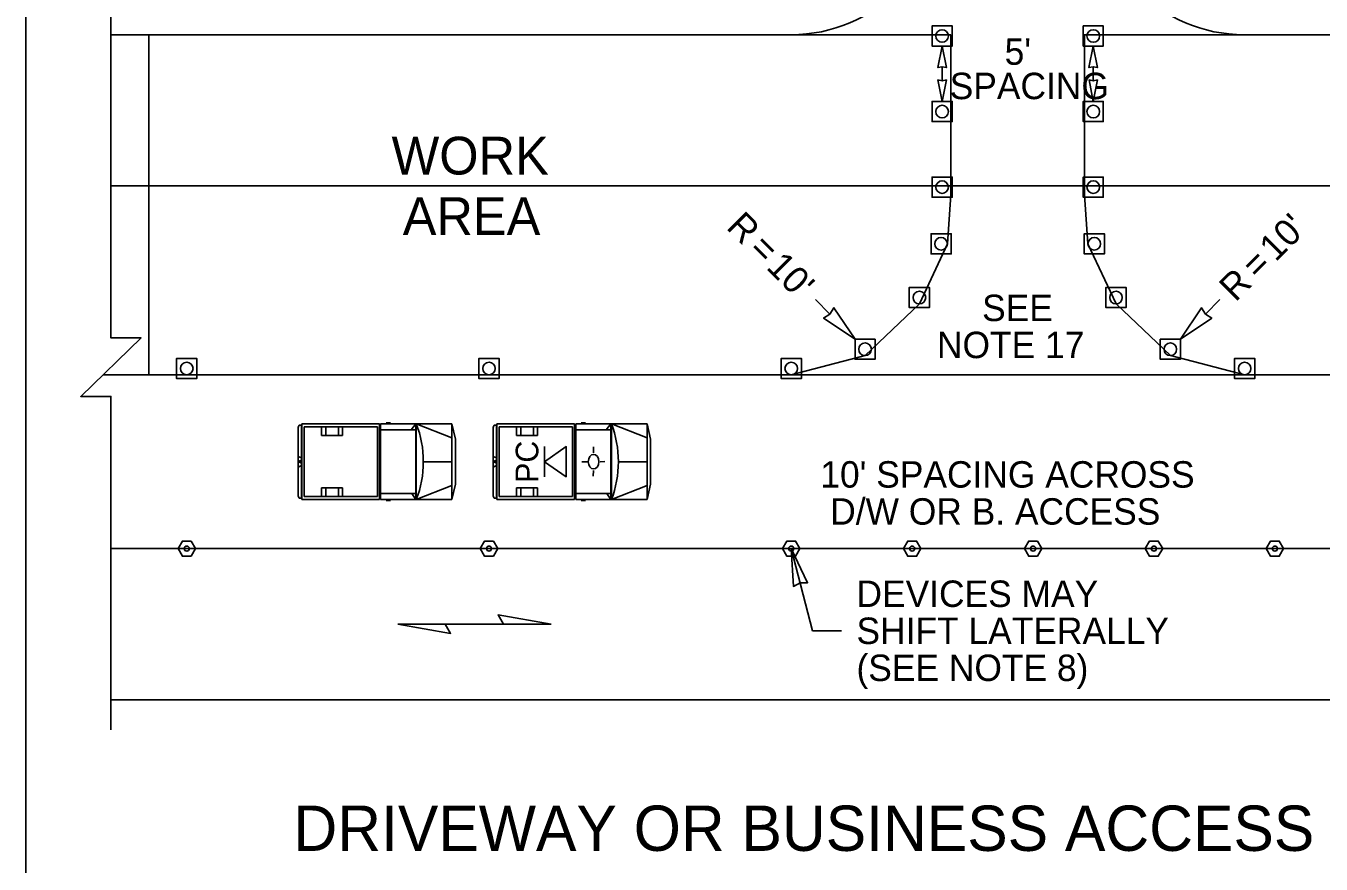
# Model space of a CAD drawing. Extents: x 99999.1 to 100095.7, y 99995 to 100010.7.
# Drawn here: x 100070.5 to 100073.928, y 100006.235 to 100008.454 of the extents above; entities that cross this region are included whole.
import ezdxf

# ---------------------------------------------------------------- set-up
doc = ezdxf.new("R2010")
doc.units = 0
for name, color, linetype in [('RD_ED_DrivewayEdge', 7, 'Continuous'), ('RD_ED_ShoulderPavedEdge', 7, 'Continuous'), ('RD_MK_LineEdgeWhite', 7, 'Continuous'), ('RD_MK_LineSkipCenter', 7, 'Continuous'), ('SH_DE_DetailHeading2Text', 7, 'Continuous'), ('TR_WZ_MotoristVehicle', 7, 'Continuous'), ('TR_WZ_PortableSignMountBlk-Wht', 7, 'Continuous'), ('TR_WZ_TrafficCone', 7, 'Continuous'), ('TR_WZ_TubularMarker', 7, 'Continuous'), ('TR_WZ_WorkAreaLabel', 7, 'Continuous'), ('TR_WZ_WorkZoneDetails', 7, 'Continuous'), ('TR_WZ_WorkZoneTextCurrent', 7, 'Continuous')]:
    doc.layers.add(name, color=color, linetype=linetype)

msp = doc.modelspace()

# ---------------------------------------------------------------- linework, layer by layer
at = {"layer": 'RD_ED_DrivewayEdge'}
for centre, start, end in [((100072.525, 100008.8304), 270, 0), ((100073.725, 100008.8304), 180, 270)]:
    msp.add_arc(centre, 0.4, start, end, dxfattribs=at)
at = {"layer": 'RD_ED_ShoulderPavedEdge'}
for p, q in [((100070.725, 100008.4305), (100072.525, 100008.4305)), ((100073.725, 100008.4305), (100075.525, 100008.4305)), ((100070.725, 100006.6704), (100075.525, 100006.6704))]:
    msp.add_line(p, q, dxfattribs=at)
at = {"layer": 'RD_MK_LineEdgeWhite'}
for p, q in [((100070.725, 100008.0305), (100075.525, 100008.0305)), ((100070.725, 100007.0704), (100075.525, 100007.0704))]:
    msp.add_line(p, q, dxfattribs=at)
at = {"layer": 'RD_MK_LineSkipCenter'}
msp.add_lwpolyline([(100075.5043, 100007.5305), (100070.7043, 100007.5305)], dxfattribs=at)
at = {"layer": 'TR_WZ_MotoristVehicle'}
for p, q in [((100071.2207, 100007.3911), (100071.2207, 100007.2098)), ((100071.2252, 100007.3972), (100071.2297, 100007.3972)), ((100071.2297, 100007.3972), (100071.2297, 100007.2037)), ((100071.2304, 100007.4005), (100071.4361, 100007.4005)), ((100071.2304, 100007.4005), (100071.2304, 100007.2005)), ((100071.2362, 100007.3925), (100071.2362, 100007.2084)), ((100071.2362, 100007.3925), (100071.4302, 100007.3925)), ((100071.2826, 100007.3925), (100071.2826, 100007.3695)), ((100071.2936, 100007.3925), (100071.2936, 100007.3695)), ((100071.3276, 100007.3925), (100071.3276, 100007.3695)), ((100071.3375, 100007.3925), (100071.3375, 100007.3695)), ((100071.4302, 100007.3925), (100071.4302, 100007.2084)), ((100071.4361, 100007.4005), (100071.4361, 100007.2005)), ((100071.4388, 100007.4005), (100071.4388, 100007.2005)), ((100071.6277, 100007.4005), (100071.4388, 100007.4005)), ((100071.5316, 100007.385), (100071.4388, 100007.385)), ((100071.4646, 100007.4033), (100071.4533, 100007.4033)), ((100071.5316, 100007.4005), (100071.5195, 100007.385)), ((100071.5316, 100007.4005), (100071.5316, 100007.2005)), ((100071.5333, 100007.4005), (100071.5333, 100007.2005)), ((100071.6277, 100007.3638), (100071.5333, 100007.4005)), ((100071.6277, 100007.4005), (100071.6277, 100007.2005)), ((100071.6277, 100007.4005), (100071.637, 100007.3601)), ((100071.737, 100007.3911), (100071.737, 100007.2098)), ((100071.7415, 100007.3972), (100071.7459, 100007.3972)), ((100071.7459, 100007.3972), (100071.7459, 100007.2037)), ((100071.7466, 100007.4005), (100071.9523, 100007.4005)), ((100071.7466, 100007.4005), (100071.7466, 100007.2005)), ((100071.7525, 100007.3925), (100071.7525, 100007.2084)), ((100071.7525, 100007.3925), (100071.9465, 100007.3925)), ((100071.7988, 100007.3925), (100071.7988, 100007.3695)), ((100071.8098, 100007.3925), (100071.8098, 100007.3695)), ((100071.8438, 100007.3925), (100071.8438, 100007.3695)), ((100071.8538, 100007.3925), (100071.8538, 100007.3695)), ((100071.9465, 100007.3925), (100071.9465, 100007.2084)), ((100071.9523, 100007.4005), (100071.9523, 100007.2005)), ((100071.9551, 100007.4005), (100071.9551, 100007.2005)), ((100072.144, 100007.4005), (100071.9551, 100007.4005)), ((100072.0478, 100007.385), (100071.9551, 100007.385)), ((100071.9809, 100007.4033), (100071.9695, 100007.4033)), ((100072.0478, 100007.4005), (100072.0358, 100007.385)), ((100072.0478, 100007.4005), (100072.0478, 100007.2005)), ((100072.0495, 100007.4005), (100072.0495, 100007.2005)), ((100072.144, 100007.3638), (100072.0495, 100007.4005)), ((100072.144, 100007.4005), (100072.144, 100007.2005)), ((100072.144, 100007.4005), (100072.1533, 100007.3601)), ((100071.2826, 100007.3695), (100071.3375, 100007.3695)), ((100071.637, 100007.3601), (100071.637, 100007.2408)), ((100071.7988, 100007.3695), (100071.8538, 100007.3695)), ((100072.0025, 100007.3401), (100072.0025, 100007.3239)), ((100072.1533, 100007.3601), (100072.1533, 100007.2408)), ((100071.2207, 100007.3145), (100071.2297, 100007.3108)), ((100071.2252, 100007.3033), (100071.2252, 100007.2976)), ((100071.737, 100007.3145), (100071.7459, 100007.3108)), ((100071.7415, 100007.3033), (100071.7415, 100007.2976)), ((100071.2207, 100007.2864), (100071.2297, 100007.2901)), ((100071.2231, 100007.3005), (100071.2273, 100007.3005)), ((100071.6277, 100007.3005), (100071.5518, 100007.3005)), ((100071.737, 100007.2864), (100071.7459, 100007.2901)), ((100071.7394, 100007.3005), (100071.7435, 100007.3005)), ((100071.9716, 100007.2997), (100071.9865, 100007.3001)), ((100071.9884, 100007.3001), (100071.9884, 100007.3001)), ((100072.0018, 100007.262), (100072.0021, 100007.277)), ((100072.0326, 100007.3006), (100072.02, 100007.3005)), ((100072.144, 100007.3005), (100072.0681, 100007.3005)), ((100071.6277, 100007.2371), (100071.5333, 100007.2005)), ((100071.6277, 100007.2005), (100071.637, 100007.2408)), ((100072.144, 100007.2371), (100072.0495, 100007.2005)), ((100072.144, 100007.2005), (100072.1533, 100007.2408)), ((100071.2252, 100007.2037), (100071.2297, 100007.2037)), ((100071.2304, 100007.2005), (100071.4361, 100007.2005)), ((100071.2362, 100007.2084), (100071.4302, 100007.2084)), ((100071.2826, 100007.2084), (100071.2826, 100007.2314)), ((100071.2826, 100007.2314), (100071.3375, 100007.2314)), ((100071.2936, 100007.2084), (100071.2936, 100007.2314)), ((100071.3276, 100007.2084), (100071.3276, 100007.2314)), ((100071.3375, 100007.2084), (100071.3375, 100007.2314)), ((100071.5316, 100007.216), (100071.4388, 100007.216)), ((100071.6277, 100007.2005), (100071.4388, 100007.2005)), ((100071.5216, 100007.216), (100071.5316, 100007.2005)), ((100071.7415, 100007.2037), (100071.7459, 100007.2037)), ((100071.7466, 100007.2005), (100071.9523, 100007.2005)), ((100071.7525, 100007.2084), (100071.9465, 100007.2084)), ((100071.7988, 100007.2084), (100071.7988, 100007.2314)), ((100071.7988, 100007.2314), (100071.8538, 100007.2314)), ((100071.8098, 100007.2084), (100071.8098, 100007.2314)), ((100071.8438, 100007.2084), (100071.8438, 100007.2314)), ((100071.8538, 100007.2084), (100071.8538, 100007.2314)), ((100072.0478, 100007.216), (100071.9551, 100007.216)), ((100072.144, 100007.2005), (100071.9551, 100007.2005)), ((100072.0379, 100007.216), (100072.0478, 100007.2005)), ((100071.4646, 100007.1976), (100071.4533, 100007.1976)), ((100071.9809, 100007.1976), (100071.9695, 100007.1976))]:
    msp.add_line(p, q, dxfattribs=at)
for centre, major_axis, start_param, end_param in [((100071.2252, 100007.3911), (0, 0.0061), 6.283185, 7.853982), ((100071.3983, 100007.3004), (0, 0.2099), 4.215852, 5.209111), ((100071.7415, 100007.3911), (0, 0.0061), 6.283185, 7.853982), ((100071.9146, 100007.3004), (0, 0.2099), 4.215852, 5.209111), ((100071.2252, 100007.2098), (0, -0.0061), 4.712389, 6.283185), ((100071.7415, 100007.2098), (0, -0.0061), 4.712389, 6.283185)]:
    msp.add_ellipse(centre, major_axis=major_axis, ratio=0.73155, start_param=start_param, end_param=end_param, dxfattribs=at)
for centre, major_axis in [((100071.2252, 100007.3005), (0, -0.00282)), ((100071.7415, 100007.3005), (0, -0.00282)), ((100072.0025, 100007.3005), (0, -0.0193))]:
    msp.add_ellipse(centre, major_axis=major_axis, ratio=0.73155, dxfattribs=at)
at = {"layer": 'TR_WZ_PortableSignMountBlk-Wht'}
msp.add_line((100071.8727, 100007.3404), (100071.8727, 100007.2604), dxfattribs=at)
msp.add_lwpolyline([(100071.8727, 100007.3004), (100071.9301, 100007.2604), (100071.9301, 100007.3404)], close=True, dxfattribs=at)
at = {"layer": 'TR_WZ_TrafficCone'}
for points in [[(100072.8984, 100008.4538), (100072.9517, 100008.4538), (100072.9517, 100008.4005), (100072.8984, 100008.4005), (100072.8984, 100008.4538)], [(100072.8984, 100008.4005), (100072.9517, 100008.4005), (100072.9517, 100008.4538), (100072.8984, 100008.4538), (100072.8984, 100008.4005)], [(100073.2983, 100008.4538), (100073.3516, 100008.4538), (100073.3516, 100008.4005), (100073.2983, 100008.4005), (100073.2983, 100008.4538)], [(100073.2983, 100008.4005), (100073.3516, 100008.4005), (100073.3516, 100008.4538), (100073.2983, 100008.4538), (100073.2983, 100008.4005)], [(100072.8984, 100008.2538), (100072.9517, 100008.2538), (100072.9517, 100008.2005), (100072.8984, 100008.2005), (100072.8984, 100008.2538)], [(100072.8984, 100008.2005), (100072.9517, 100008.2005), (100072.9517, 100008.2538), (100072.8984, 100008.2538), (100072.8984, 100008.2005)], [(100073.2983, 100008.2538), (100073.3516, 100008.2538), (100073.3516, 100008.2005), (100073.2983, 100008.2005), (100073.2983, 100008.2538)], [(100073.2983, 100008.2005), (100073.3516, 100008.2005), (100073.3516, 100008.2538), (100073.2983, 100008.2538), (100073.2983, 100008.2005)], [(100072.8984, 100008.0538), (100072.9517, 100008.0538), (100072.9517, 100008.0005), (100072.8984, 100008.0005), (100072.8984, 100008.0538)], [(100072.8984, 100008.0005), (100072.9517, 100008.0005), (100072.9517, 100008.0538), (100072.8984, 100008.0538), (100072.8984, 100008.0005)], [(100073.2983, 100008.0538), (100073.3516, 100008.0538), (100073.3516, 100008.0005), (100073.2983, 100008.0005), (100073.2983, 100008.0538)], [(100073.2983, 100008.0005), (100073.3516, 100008.0005), (100073.3516, 100008.0538), (100073.2983, 100008.0538), (100073.2983, 100008.0005)], [(100072.8956, 100007.9038), (100072.949, 100007.9038), (100072.949, 100007.8505), (100072.8956, 100007.8505), (100072.8956, 100007.9038)], [(100072.8956, 100007.8505), (100072.949, 100007.8505), (100072.949, 100007.9038), (100072.8956, 100007.9038), (100072.8956, 100007.8505)], [(100073.301, 100007.9038), (100073.3544, 100007.9038), (100073.3544, 100007.8505), (100073.301, 100007.8505), (100073.301, 100007.9038)], [(100073.301, 100007.8505), (100073.3544, 100007.8505), (100073.3544, 100007.9038), (100073.301, 100007.9038), (100073.301, 100007.8505)], [(100072.8381, 100007.7615), (100072.8914, 100007.7615), (100072.8914, 100007.7082), (100072.8381, 100007.7082), (100072.8381, 100007.7615)], [(100072.8381, 100007.7082), (100072.8914, 100007.7082), (100072.8914, 100007.7615), (100072.8381, 100007.7615), (100072.8381, 100007.7082)], [(100073.3586, 100007.7615), (100073.4119, 100007.7615), (100073.4119, 100007.7082), (100073.3586, 100007.7082), (100073.3586, 100007.7615)], [(100073.3586, 100007.7082), (100073.4119, 100007.7082), (100073.4119, 100007.7615), (100073.3586, 100007.7615), (100073.3586, 100007.7082)], [(100072.6944, 100007.6247), (100072.7477, 100007.6247), (100072.7477, 100007.5714), (100072.6944, 100007.5714), (100072.6944, 100007.6247)], [(100072.6944, 100007.5714), (100072.7477, 100007.5714), (100072.7477, 100007.6247), (100072.6944, 100007.6247), (100072.6944, 100007.5714)], [(100073.5023, 100007.6247), (100073.5556, 100007.6247), (100073.5556, 100007.5714), (100073.5023, 100007.5714), (100073.5023, 100007.6247)], [(100073.5023, 100007.5714), (100073.5556, 100007.5714), (100073.5556, 100007.6247), (100073.5023, 100007.6247), (100073.5023, 100007.5714)], [(100070.899, 100007.5738), (100070.9524, 100007.5738), (100070.9524, 100007.5205), (100070.899, 100007.5205), (100070.899, 100007.5738)], [(100070.899, 100007.5205), (100070.9524, 100007.5205), (100070.9524, 100007.5738), (100070.899, 100007.5738), (100070.899, 100007.5205)], [(100071.699, 100007.5738), (100071.7524, 100007.5738), (100071.7524, 100007.5205), (100071.699, 100007.5205), (100071.699, 100007.5738)], [(100071.699, 100007.5205), (100071.7524, 100007.5205), (100071.7524, 100007.5738), (100071.699, 100007.5738), (100071.699, 100007.5205)], [(100072.499, 100007.5738), (100072.5524, 100007.5738), (100072.5524, 100007.5205), (100072.499, 100007.5205), (100072.499, 100007.5738)], [(100072.499, 100007.5205), (100072.5524, 100007.5205), (100072.5524, 100007.5738), (100072.499, 100007.5738), (100072.499, 100007.5205)], [(100073.699, 100007.5738), (100073.7524, 100007.5738), (100073.7524, 100007.5205), (100073.699, 100007.5205), (100073.699, 100007.5738)], [(100073.699, 100007.5205), (100073.7524, 100007.5205), (100073.7524, 100007.5738), (100073.699, 100007.5738), (100073.699, 100007.5205)]]:
    msp.add_lwpolyline(points, dxfattribs=at)
for centre in [(100072.925, 100008.4271), (100073.325, 100008.4271), (100072.925, 100008.2271), (100073.325, 100008.2271), (100072.925, 100008.0271), (100073.325, 100008.0271), (100072.9223, 100007.8771), (100073.3277, 100007.8771), (100072.8648, 100007.7349), (100073.3852, 100007.7349), (100072.721, 100007.598), (100073.529, 100007.598), (100070.9257, 100007.5471), (100071.7257, 100007.5471), (100072.5257, 100007.5471), (100073.7257, 100007.5471)]:
    msp.add_circle(centre, 0.0167, dxfattribs=at)
at = {"layer": 'TR_WZ_TubularMarker'}
for points in [[(100070.9026, 100007.0704), (100070.9142, 100007.0904), (100070.9373, 100007.0904), (100070.9488, 100007.0704), (100070.9373, 100007.0504), (100070.9142, 100007.0504)], [(100071.7026, 100007.0704), (100071.7141, 100007.0904), (100071.7372, 100007.0904), (100071.7488, 100007.0704), (100071.7372, 100007.0504), (100071.7141, 100007.0504)], [(100072.5026, 100007.0704), (100072.5141, 100007.0904), (100072.5372, 100007.0904), (100072.5488, 100007.0704), (100072.5372, 100007.0504), (100072.5141, 100007.0504)], [(100072.8226, 100007.0704), (100072.8341, 100007.0904), (100072.8572, 100007.0904), (100072.8688, 100007.0704), (100072.8572, 100007.0504), (100072.8341, 100007.0504)], [(100073.1426, 100007.0704), (100073.1541, 100007.0904), (100073.1772, 100007.0904), (100073.1888, 100007.0704), (100073.1772, 100007.0504), (100073.1541, 100007.0504)], [(100073.4626, 100007.0704), (100073.4741, 100007.0904), (100073.4972, 100007.0904), (100073.5088, 100007.0704), (100073.4972, 100007.0504), (100073.4741, 100007.0504)], [(100073.7826, 100007.0704), (100073.7941, 100007.0904), (100073.8172, 100007.0904), (100073.8288, 100007.0704), (100073.8172, 100007.0504), (100073.7941, 100007.0504)]]:
    msp.add_lwpolyline(points, close=True, dxfattribs=at)
for points in [[(100070.9142, 100007.0504), (100070.9373, 100007.0504), (100070.9488, 100007.0704), (100070.9373, 100007.0904), (100070.9142, 100007.0904), (100070.9026, 100007.0704), (100070.9142, 100007.0504)], [(100071.7141, 100007.0504), (100071.7372, 100007.0504), (100071.7488, 100007.0704), (100071.7372, 100007.0904), (100071.7141, 100007.0904), (100071.7026, 100007.0704), (100071.7141, 100007.0504)], [(100072.5141, 100007.0504), (100072.5372, 100007.0504), (100072.5488, 100007.0704), (100072.5372, 100007.0904), (100072.5141, 100007.0904), (100072.5026, 100007.0704), (100072.5141, 100007.0504)], [(100072.8341, 100007.0504), (100072.8572, 100007.0504), (100072.8688, 100007.0704), (100072.8572, 100007.0904), (100072.8341, 100007.0904), (100072.8226, 100007.0704), (100072.8341, 100007.0504)], [(100073.1541, 100007.0504), (100073.1772, 100007.0504), (100073.1888, 100007.0704), (100073.1772, 100007.0904), (100073.1541, 100007.0904), (100073.1426, 100007.0704), (100073.1541, 100007.0504)], [(100073.4741, 100007.0504), (100073.4972, 100007.0504), (100073.5088, 100007.0704), (100073.4972, 100007.0904), (100073.4741, 100007.0904), (100073.4626, 100007.0704), (100073.4741, 100007.0504)], [(100073.7941, 100007.0504), (100073.8172, 100007.0504), (100073.8288, 100007.0704), (100073.8172, 100007.0904), (100073.7941, 100007.0904), (100073.7826, 100007.0704), (100073.7941, 100007.0504)]]:
    msp.add_lwpolyline(points, dxfattribs=at)
for centre in [(100070.9257, 100007.0704), (100071.7257, 100007.0704), (100072.5257, 100007.0704), (100072.8457, 100007.0704), (100073.1657, 100007.0704), (100073.4857, 100007.0704), (100073.8057, 100007.0704)]:
    msp.add_circle(centre, 0.00667, dxfattribs=at)
at = {"layer": 'TR_WZ_WorkZoneDetails'}
for p, q in [((100070.5, 100010.275), (100070.5, 100001.6859)), ((100072.9251, 100008.3459), (100072.9251, 100008.3083)), ((100073.325, 100008.3459), (100073.325, 100008.3083)), ((100072.6281, 100007.691), (100072.5897, 100007.7294)), ((100073.6219, 100007.691), (100073.6603, 100007.7294)), ((100072.5257, 100007.0704), (100072.5821, 100006.853)), ((100071.7642, 100006.8704), (100071.6098, 100006.8704)), ((100071.6098, 100006.8704), (100071.7642, 100006.8704)), ((100072.6583, 100006.853), (100072.5821, 100006.853))]:
    msp.add_line(p, q, dxfattribs=at)
msp.add_lwpolyline([(100070.725, 100006.5904), (100070.725, 100007.473), (100070.645, 100007.473), (100070.805, 100007.6279), (100070.725, 100007.6279), (100070.725, 100008.5105)], dxfattribs=at)
for points in [[(100072.9483, 100008.4305), (100072.9483, 100008.2071), (100072.9483, 100008.0071), (100072.939, 100007.8771), (100072.939, 100007.8771), (100072.939, 100007.8771), (100072.8648, 100007.7182), (100072.8648, 100007.7182), (100072.8648, 100007.7182), (100072.721, 100007.5814), (100072.5257, 100007.5305), (100071.529, 100007.5305), (100070.949, 100007.5305), (100070.825, 100007.5305), (100070.825, 100008.4305)], [(100072.925, 100008.4005), (100072.9363, 100008.3433), (100072.925, 100008.3459), (100072.9138, 100008.3433)], [(100075.425, 100008.4305), (100075.425, 100008.0305), (100075.425, 100007.5305), (100074.501, 100007.5305), (100074.501, 100007.5305), (100074.501, 100007.5305), (100073.7257, 100007.5305), (100073.7257, 100007.5305), (100073.7257, 100007.5305), (100073.529, 100007.5814), (100073.3852, 100007.7182), (100073.311, 100007.8771), (100073.3017, 100008.0071), (100073.3017, 100008.2071), (100073.3017, 100008.4305)], [(100073.325, 100008.4005), (100073.3362, 100008.3433), (100073.325, 100008.3459), (100073.3137, 100008.3433)], [(100072.9251, 100008.2538), (100072.9363, 100008.3109), (100072.9251, 100008.3083), (100072.9139, 100008.3109)], [(100073.325, 100008.2538), (100073.3362, 100008.3109), (100073.325, 100008.3083), (100073.3138, 100008.3109)], [(100072.6944, 100007.6247), (100072.6113, 100007.6806), (100072.6281, 100007.691), (100072.6385, 100007.7079)], [(100073.5556, 100007.6247), (100073.6387, 100007.6806), (100073.6219, 100007.691), (100073.6115, 100007.7079)], [(100072.5257, 100007.0704), (100072.569, 100006.9801), (100072.5492, 100006.9797), (100072.5316, 100006.9705)], [(100071.8899, 100006.8704), (100071.7499, 100006.8951), (100071.7642, 100006.8704)], [(100071.4841, 100006.8704), (100071.6241, 100006.8458), (100071.6098, 100006.8704)]]:
    msp.add_lwpolyline(points, close=True, dxfattribs=at)

# ---------------------------------------------------------------- texts
at = {"layer": 'SH_DE_DetailHeading2Text'}
msp.add_text('DRIVEWAY OR BUSINESS ACCESS DETAIL', height=0.12, rotation=360, dxfattribs=at).set_placement((100071.2082, 100006.2704))
at = {"layer": 'TR_WZ_MotoristVehicle'}
msp.add_text('PC', height=0.06, rotation=90, dxfattribs=at).set_placement((100071.8563, 100007.2444))
at = {"layer": 'TR_WZ_WorkAreaLabel'}
for s, p in [('WORK', (100071.4678, 100008.0605)), ('AREA', (100071.4974, 100007.9004))]:
    msp.add_text(s, height=0.1, dxfattribs=at).set_placement(p)
at = {"layer": 'TR_WZ_WorkZoneTextCurrent'}
for s, p in [("5'", (100073.0904, 100008.3509)), ('SPACING', (100072.945, 100008.2599)), ('SEE', (100073.0308, 100007.6725)), ('NOTE 17', (100072.9113, 100007.5745)), ("10' SPACING ACROSS", (100072.6026, 100007.2318)), ('D/W OR B. ACCESS', (100072.6288, 100007.1338)), ('DEVICES MAY', (100072.6983, 100006.916)), ('SHIFT LATERALLY', (100072.6983, 100006.818)), ('(SEE NOTE 8)', (100072.6983, 100006.72))]:
    msp.add_text(s, height=0.07, dxfattribs=at).set_placement(p)
for s, rotation, p in [('R', 315, (100072.3509, 100007.9186)), ("10'", 45, (100073.8075, 100007.8271)), ('=', 315, (100072.4101, 100007.8595)), ('=', 45, (100073.7606, 100007.7802)), ("10'", 315, (100072.457, 100007.8126)), ('R', 45, (100073.7015, 100007.7211))]:
    msp.add_text(s, height=0.07, rotation=rotation, dxfattribs=at).set_placement(p)

doc.saveas('drawing.dxf')
